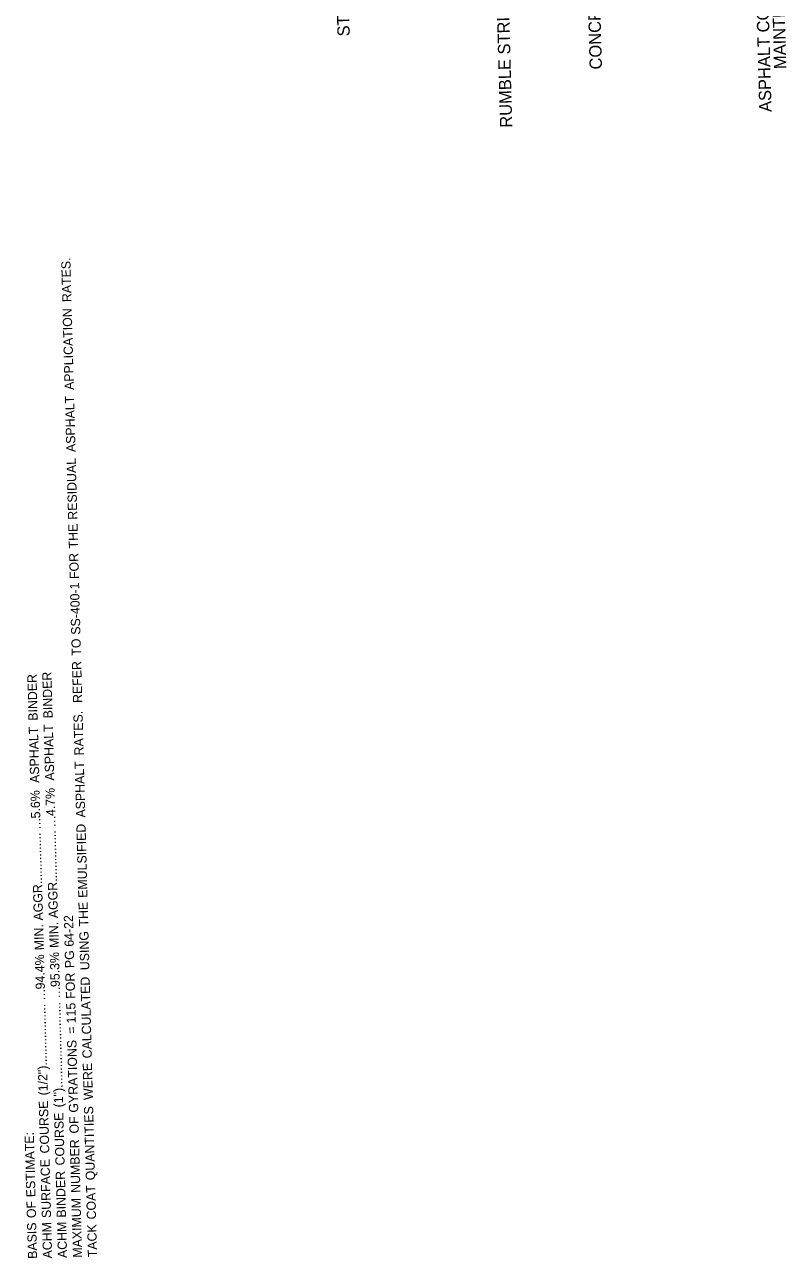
# Model space of a CAD drawing. Extents: x 1930091 to 1931962, y 596452 to 607874.
# Drawn here: x 1931190 to 1931685, y 601453 to 602254 of the extents above; entities that cross this region are included whole.
import ezdxf

# ---------------------------------------------------------------- set-up
doc = ezdxf.new("R2010")
doc.units = 0
doc.layers.add('Default', color=7, linetype='Continuous')

msp = doc.modelspace()

# ---------------------------------------------------------------- texts
at = {"layer": 'Default'}
for s, height, p in [('RUMBLE STRIPS IN ASPHALT SHOULDERS', 8, (1931506.73, 602187.56)), ('ASPHALT CONCRETE PATCHING FOR', 8, (1931675.21, 602197.75)), ('MAINTENANCE OF TRAFFIC', 8, (1931684.82, 602225.62)), ('CONCRETE DITCH PAVING', 8, (1931565.01, 602225.36)), ('STRUCTURES', 8, (1931401.1, 602246.86)), (' RATES.', 6, (1931220.3, 602071.98)), (' APPLICATION', 6, (1931221.83, 602014.91)), (' ASPHALT', 6, (1931222.92, 601974.56)), (' RESIDUAL', 6, (1931224.09, 601930.61)), (' THE', 6, (1931224.6, 601911.97)), (' FOR', 6, (1931225.13, 601892.07)), (' SS-400-1', 6, (1931226.1, 601855.89)), (' TO', 6, (1931226.47, 601842.3)), ('  REFER', 6, (1931227.35, 601809.35)), (' BINDER', 6, (1931198.34, 601800.04)), (' BINDER', 6, (1931208.05, 601801.56)), (' RATES.', 6, (1931228.21, 601777.48)), ('  ASPHALT', 6, (1931209.2, 601758.88)), ('  ASPHALT', 6, (1931199.49, 601757.36)), (' ASPHALT', 6, (1931229.29, 601737.13)), ('4.7%', 6, (1931209.7, 601740.3)), ('5.6%', 6, (1931199.98, 601738.79)), ('…', 6, (1931200.18, 601731.39)), ('…', 6, (1931209.9, 601732.91)), (' EMULSIFIED', 6, (1931230.69, 601684.96)), (' AGGR...............', 6, (1931201.82, 601670.21)), (' AGGR...............', 6, (1931211.54, 601671.73)), (' THE', 6, (1931231.19, 601666.32)), (' MIN.', 6, (1931212.06, 601652.44)), (' 64-22', 6, (1931221.79, 601653.21)), (' MIN.', 6, (1931202.34, 601650.93)), (' USING', 6, (1931231.95, 601637.97)), ('94.4%', 6, (1931202.97, 601627.7)), ('95.3%', 6, (1931212.68, 601629.21)), (' PG', 6, (1931222.16, 601639.3)), (' FOR', 6, (1931222.7, 601619.39)), (' CALCULATED', 6, (1931233.49, 601580.67)), ('…', 6, (1931203.16, 601620.3)), ('…', 6, (1931212.88, 601621.82)), (' (1/2")..................', 6, (1931204.87, 601556.62)), (' (1").........................', 6, (1931214.84, 601548.84)), (' 115', 6, (1931223.12, 601603.42)), (' =', 6, (1931223.31, 601596.67)), (' GYRATIONS', 6, (1931224.68, 601545.42)), (' WERE', 6, (1931234.21, 601553.65)), (' COURSE', 6, (1931205.89, 601518.89)), (' QUANTITIES', 6, (1931235.61, 601501.47)), (' COURSE', 6, (1931215.85, 601511.1)), (' OF', 6, (1931225.05, 601531.84)), (' ESTIMATE:', 6, (1931196.9, 601490.48)), (' NUMBER', 6, (1931226.08, 601493.31)), (' SURFACE', 6, (1931207.01, 601476.96)), (' BINDER', 6, (1931216.76, 601477.22)), (' COAT', 6, (1931236.3, 601476.03)), (' OF', 6, (1931197.26, 601476.9)), ('MAXIMUM', 6, (1931227.15, 601453.43)), ('BASIS', 6, (1931197.91, 601452.65)), ('ACHM', 6, (1931207.66, 601452.91)), ('ACHM', 6, (1931217.4, 601453.17)), ('TACK', 6, (1931236.9, 601453.69))]:
    msp.add_text(s, height=height, rotation=91.53769, dxfattribs=at).set_placement(p)

doc.saveas('drawing.dxf')
